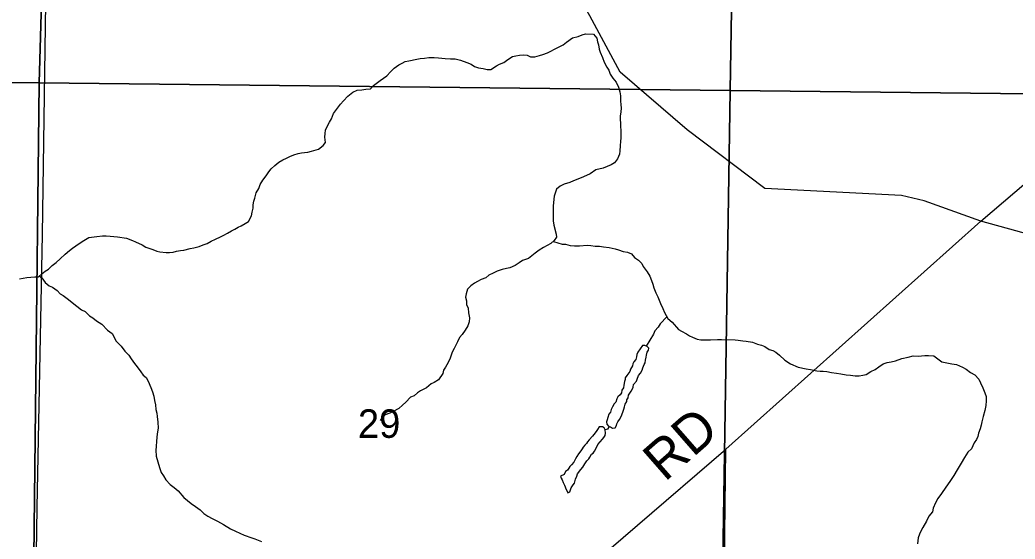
# Model space of a CAD drawing. Extents: x 0 to 34, y 0 to 22.
# Drawn here: x 3.441 to 4.9, y 15.795 to 16.557 of the extents above; entities that cross this region are included whole.
import ezdxf

# ---------------------------------------------------------------- set-up
doc = ezdxf.new("R2010")
doc.units = 0
for name, color, linetype in [('GM_X_County_Road', 7, 'Continuous'), ('GM_X_County_Road_Text', 7, 'Continuous'), ('GM_X_Minor_Lake', 7, 'Continuous'), ('GM_X_Minor_River', 7, 'Continuous'), ('GM_X_Section', 7, 'Continuous'), ('GM_X_Section_Text', 7, 'Continuous'), ('GM_X_State_Route', 7, 'Continuous'), ('GM_X_Township_Road', 7, 'Continuous')]:
    doc.layers.add(name, color=color, linetype=linetype)

msp = doc.modelspace()

# ---------------------------------------------------------------- linework, layer by layer
at = {"layer": 'GM_X_County_Road'}
msp.add_lwpolyline([(3.9812, 15.4992), (4.2172, 15.704), (4.4759, 15.927), (4.8499, 16.2614), (4.9696, 16.3635), (5.1729, 16.5392), (5.2364, 16.5952)], dxfattribs=at)
at = {"layer": 'GM_X_Minor_Lake'}
for points in [[(4.3539, 16.0791), (4.3469, 16.069), (4.3457, 16.0656), (4.3453, 16.0622), (4.344, 16.0585), (4.3413, 16.0551), (4.3398, 16.0521), (4.3393, 16.0494), (4.3362, 16.0442), (4.3354, 16.0408), (4.3307, 16.0352), (4.3287, 16.0318), (4.3283, 16.0292), (4.3275, 16.0262), (4.3266, 16.0209), (4.3258, 16.0171), (4.3238, 16.0137), (4.323, 16.0096), (4.321, 16.0066), (4.3179, 16.0036), (4.3163, 16.0006), (4.3147, 15.9961), (4.3124, 15.9935), (4.31, 15.989), (4.3081, 15.9852), (4.3072, 15.981), (4.3045, 15.9784), (4.3029, 15.9732), (4.3021, 15.9698), (4.3013, 15.9671), (4.3016, 15.9637), (4.3042, 15.9606), (4.305, 15.9604)], [(4.305, 15.9604), (4.3068, 15.9598), (4.3098, 15.9579), (4.3139, 15.9582), (4.3159, 15.9615), (4.3163, 15.9642), (4.3175, 15.9668), (4.3203, 15.9705), (4.3222, 15.9739), (4.3234, 15.9773), (4.3254, 15.9826), (4.3263, 15.9856), (4.3275, 15.989), (4.3283, 15.9928), (4.3307, 15.9969), (4.3311, 15.9995), (4.3327, 16.0022), (4.3335, 16.0063), (4.3351, 16.0089), (4.3374, 16.0119), (4.339, 16.0153), (4.3402, 16.0179), (4.3406, 16.0217), (4.3453, 16.0266), (4.3461, 16.0296), (4.3481, 16.0349), (4.3512, 16.0386), (4.3536, 16.0427), (4.3544, 16.0461), (4.3564, 16.051), (4.3576, 16.0536), (4.3584, 16.0574), (4.3593, 16.0619), (4.3597, 16.0646), (4.3609, 16.0691), (4.3625, 16.0721), (4.3633, 16.0751), (4.3607, 16.0775), (4.3573, 16.0791), (4.3539, 16.0791)], [(4.2905, 15.9598), (4.2878, 15.956), (4.2858, 15.9526), (4.2827, 15.9485), (4.2808, 15.9459), (4.2757, 15.9407), (4.2734, 15.9377), (4.2718, 15.9351), (4.2691, 15.9329), (4.2668, 15.9299), (4.2656, 15.9272), (4.2633, 15.9246), (4.2602, 15.9202), (4.2574, 15.916), (4.2558, 15.9126), (4.2531, 15.9078), (4.25, 15.904), (4.2473, 15.9014), (4.2461, 15.8988), (4.2438, 15.8962), (4.2411, 15.894), (4.2391, 15.8898), (4.2337, 15.8873), (4.2344, 15.8846), (4.2359, 15.8819), (4.2377, 15.8781), (4.2395, 15.8743), (4.2406, 15.8716), (4.2413, 15.8689), (4.2435, 15.8655), (4.2442, 15.8628), (4.2473, 15.8643), (4.2481, 15.8673), (4.2493, 15.8703), (4.252, 15.8744), (4.254, 15.877), (4.2556, 15.8831), (4.2576, 15.8872), (4.2588, 15.8906), (4.2635, 15.8973), (4.2662, 15.9007), (4.2693, 15.9056), (4.2724, 15.9097), (4.2751, 15.9126), (4.2767, 15.9153), (4.2791, 15.9194), (4.2818, 15.9212), (4.2837, 15.9239), (4.2869, 15.9302), (4.2885, 15.934), (4.2951, 15.9415), (4.2974, 15.9441), (4.299, 15.9471), (4.2998, 15.9505), (4.2994, 15.9553)], [(4.2994, 15.9553), (4.2977, 15.9581), (4.2951, 15.9597), (4.2905, 15.9598)]]:
    msp.add_lwpolyline(points, dxfattribs=at)
at = {"layer": 'GM_X_Minor_River'}
for points in [[(3.7841, 16.2908), (3.7853, 16.2954), (3.7876, 16.303), (3.7911, 16.3094), (3.7934, 16.315), (3.7973, 16.3214), (3.8019, 16.3279), (3.8062, 16.3339), (3.8096, 16.3384), (3.8146, 16.3433), (3.8208, 16.3481), (3.8265, 16.3515), (3.8318, 16.3541), (3.8368, 16.3563), (3.8425, 16.3589), (3.849, 16.3608), (3.8539, 16.3615), (3.8585, 16.3622), (3.863, 16.3625), (3.8687, 16.3643), (3.8786, 16.3673), (3.8855, 16.3725), (3.889, 16.377), (3.8883, 16.3846), (3.8884, 16.3903), (3.8892, 16.3949), (3.8915, 16.4005), (3.895, 16.4066), (3.8977, 16.4115), (3.9008, 16.4194), (3.9112, 16.433), (3.9155, 16.4382), (3.922, 16.4446), (3.9293, 16.4506), (3.9354, 16.4536), (3.9422, 16.4543), (3.9483, 16.4553), (3.9551, 16.4557), (3.9597, 16.4605), (3.9693, 16.4677), (3.9743, 16.4714), (3.9789, 16.4748), (3.9842, 16.4804), (3.99, 16.486), (3.9965, 16.4909), (4.0014, 16.4935), (4.006, 16.4957), (4.0113, 16.4968), (4.0228, 16.499), (4.0281, 16.5), (4.0342, 16.5007), (4.0406, 16.5014), (4.0482, 16.5017), (4.055, 16.5009), (4.0645, 16.5), (4.0724, 16.4996), (4.0793, 16.4995), (4.0868, 16.4979), (4.0963, 16.494), (4.1027, 16.4917), (4.1076, 16.4886), (4.1136, 16.4866), (4.1201, 16.4854), (4.1261, 16.4838), (4.1314, 16.4838), (4.1399, 16.4894), (4.1444, 16.4916), (4.1505, 16.4942), (4.1563, 16.4987), (4.1631, 16.5028), (4.1681, 16.5042), (4.1734, 16.5049), (4.1787, 16.5056), (4.1848, 16.5052), (4.1897, 16.5025), (4.1958, 16.5024), (4.203, 16.5046), (4.2079, 16.5061), (4.2148, 16.5083), (4.2194, 16.5109), (4.2251, 16.5139), (4.2297, 16.5161), (4.2377, 16.5202), (4.2427, 16.5239), (4.2511, 16.5303), (4.2594, 16.5325), (4.2655, 16.5347), (4.2701, 16.5362), (4.2822, 16.536), (4.2871, 16.5299), (4.2878, 16.5246), (4.2893, 16.52), (4.2903, 16.5139), (4.2918, 16.5094), (4.2951, 16.5017), (4.2977, 16.4949), (4.3014, 16.4876), (4.3044, 16.483), (4.3066, 16.4773), (4.3103, 16.4712), (4.3152, 16.4655)], [(4.3152, 16.4655), (4.3189, 16.4582), (4.3207, 16.451), (4.3218, 16.4453), (4.3217, 16.4377), (4.322, 16.4324), (4.3224, 16.4274), (4.3219, 16.4217), (4.3211, 16.4157), (4.321, 16.4103), (4.3214, 16.4058), (4.3217, 16.3997), (4.322, 16.3948), (4.3219, 16.3834), (4.3218, 16.3788), (4.3213, 16.372), (4.3209, 16.3648), (4.3204, 16.3599), (4.3173, 16.3527), (4.3127, 16.347), (4.3078, 16.3441), (4.2963, 16.3392), (4.2857, 16.3367), (4.2773, 16.3307), (4.2673, 16.3263), (4.2593, 16.3229), (4.2525, 16.3207), (4.2475, 16.3181), (4.2392, 16.3159), (4.2334, 16.313), (4.2277, 16.3085), (4.2261, 16.3039), (4.2242, 16.2979), (4.2229, 16.2839), (4.2228, 16.2759), (4.2231, 16.2683), (4.223, 16.2618), (4.2237, 16.2554), (4.2273, 16.2424), (4.228, 16.2379), (4.2246, 16.233), (4.2196, 16.2285), (4.2142, 16.2259), (4.2085, 16.2229), (4.2024, 16.2188), (4.1967, 16.2147), (4.1867, 16.2068), (4.1779, 16.2039), (4.173, 16.2001), (4.1672, 16.1964), (4.1592, 16.193), (4.1543, 16.192), (4.1482, 16.1905), (4.141, 16.1879), (4.1349, 16.1853), (4.1288, 16.182), (4.1242, 16.1782), (4.1173, 16.1757), (4.112, 16.1727), (4.1074, 16.1704), (4.102, 16.1667), (4.0971, 16.1618), (4.0955, 16.1546), (4.0946, 16.1501), (4.0957, 16.1444), (4.096, 16.1394), (4.0982, 16.1337), (4.0989, 16.1269), (4.1, 16.1197), (4.0999, 16.1136), (4.0976, 16.1079), (4.0937, 16.1015), (4.0895, 16.0951), (4.0856, 16.0906), (4.0825, 16.0842), (4.0775, 16.0747), (4.0748, 16.0691), (4.072, 16.0604), (4.0689, 16.0539), (4.065, 16.0471), (4.0623, 16.0426), (4.0611, 16.0381), (4.0549, 16.0287), (4.0485, 16.0249), (4.0439, 16.0227), (4.037, 16.0167), (4.0286, 16.0126), (4.024, 16.0096), (4.019, 16.0051), (4.0137, 16.0033), (4.0068, 15.9961), (4.0022, 15.9916), (3.9968, 15.9868), (3.9884, 15.9823), (3.9835, 15.9797), (3.9766, 15.9771), (3.972, 15.9734), (3.9693, 15.9688)], [(3.4406, 16.1769), (3.4459, 16.1779), (3.4513, 16.1786), (3.457, 16.1793), (3.463, 16.1797), (3.468, 16.18), (3.4733, 16.1841), (3.4779, 16.1882), (3.4829, 16.1912), (3.4883, 16.1965), (3.494, 16.201), (3.4998, 16.2062), (3.5074, 16.213), (3.5135, 16.2182), (3.5181, 16.2216), (3.5231, 16.2253), (3.5277, 16.2287), (3.5346, 16.2332), (3.5422, 16.2373), (3.5536, 16.239), (3.562, 16.2397), (3.5673, 16.2397), (3.5733, 16.2392), (3.5839, 16.2383), (3.5972, 16.2363), (3.6059, 16.2332), (3.6104, 16.2312), (3.6202, 16.2269), (3.6255, 16.2231), (3.6357, 16.2199), (3.6417, 16.2176), (3.6463, 16.2164), (3.6554, 16.2155), (3.6603, 16.2155), (3.6656, 16.2162), (3.6706, 16.2173), (3.6763, 16.2184), (3.6812, 16.2191), (3.6907, 16.2212), (3.696, 16.2223), (3.7037, 16.2245), (3.7097, 16.2267), (3.7155, 16.2289), (3.7216, 16.2319), (3.728, 16.2349), (3.7349, 16.2386), (3.7399, 16.2408), (3.7452, 16.2438), (3.7513, 16.2472), (3.7559, 16.2498), (3.7609, 16.2524), (3.7654, 16.2546), (3.7712, 16.258), (3.7761, 16.2609), (3.7804, 16.2692), (3.7816, 16.2745), (3.7828, 16.2806), (3.7832, 16.2855), (3.7841, 16.2908)], [(4.2233, 16.2318), (4.2359, 16.2279), (4.2408, 16.2275), (4.248, 16.2259), (4.2544, 16.2251), (4.2613, 16.2254), (4.2726, 16.226), (4.2783, 16.2256), (4.2844, 16.2247), (4.2908, 16.225), (4.2969, 16.2238), (4.3049, 16.223), (4.3139, 16.221), (4.3185, 16.2194), (4.3257, 16.2171), (4.3317, 16.2159), (4.3377, 16.2135), (4.3422, 16.2082), (4.3479, 16.2043), (4.3528, 16.1993), (4.355, 16.1947), (4.3606, 16.1871), (4.3647, 16.1806), (4.3673, 16.1745), (4.3691, 16.1692), (4.3706, 16.1634), (4.3735, 16.1562), (4.3765, 16.1505), (4.3783, 16.1455), (4.3805, 16.1406), (4.3839, 16.1333), (4.3861, 16.1272), (4.3909, 16.1184), (4.3973, 16.1134), (4.4067, 16.1023), (4.4112, 16.1), (4.4183, 16.0961), (4.4229, 16.093), (4.4274, 16.0911), (4.4342, 16.0884), (4.4395, 16.0875), (4.4535, 16.0874), (4.4641, 16.0877), (4.4698, 16.0876), (4.4896, 16.0874), (4.4941, 16.087), (4.5009, 16.0861), (4.5058, 16.0853), (4.5153, 16.0837), (4.5225, 16.081), (4.5282, 16.0794), (4.5331, 16.0774), (4.5395, 16.0732), (4.5448, 16.0716), (4.5493, 16.0693), (4.5549, 16.0647), (4.5628, 16.0574), (4.5707, 16.0523), (4.5824, 16.0473), (4.5938, 16.0449), (4.6002, 16.0437), (4.6097, 16.0417), (4.6142, 16.0413), (4.6188, 16.0412), (4.6241, 16.0408), (4.6309, 16.0396), (4.6385, 16.0383), (4.6445, 16.0375), (4.6525, 16.0359), (4.6589, 16.0355), (4.6657, 16.0346), (4.6718, 16.0346), (4.6771, 16.0356), (4.6817, 16.0367), (4.6885, 16.0408), (4.695, 16.0438), (4.7004, 16.0475), (4.7069, 16.052), (4.7126, 16.0542), (4.7183, 16.0553), (4.7251, 16.0564), (4.7343, 16.0601), (4.7434, 16.0619), (4.751, 16.0637), (4.7586, 16.0636), (4.7632, 16.064), (4.7681, 16.0643), (4.7734, 16.0642), (4.781, 16.0638), (4.793, 16.0553), (4.8025, 16.0529), (4.8074, 16.0521), (4.8142, 16.0509), (4.8188, 16.0493), (4.8233, 16.0474), (4.8286, 16.0443), (4.835, 16.0396), (4.841, 16.0358), (4.847, 16.0296), (4.8496, 16.0243), (4.8529, 16.0167)], [(3.4693, 16.181), (3.4729, 16.1784), (3.4781, 16.1715), (3.4841, 16.1665), (3.4887, 16.1646), (3.4954, 16.1596), (3.4999, 16.1546), (3.5044, 16.1523), (3.5123, 16.1465), (3.5176, 16.1422), (3.5244, 16.1365), (3.5311, 16.1315), (3.5368, 16.1287), (3.5432, 16.1226), (3.5477, 16.1195), (3.5533, 16.1153), (3.5613, 16.1103), (3.5695, 16.1014), (3.5763, 16.0968), (3.5822, 16.0854), (3.5893, 16.0781), (3.5949, 16.0708), (3.6006, 16.065), (3.6039, 16.0593), (3.6091, 16.0524), (3.6129, 16.0475), (3.6185, 16.0406), (3.6215, 16.0356), (3.626, 16.0321), (3.629, 16.0268), (3.633, 16.0172), (3.6352, 16.0111), (3.6374, 16.0047), (3.6381, 15.9982), (3.6396, 15.9921), (3.6402, 15.9849), (3.6417, 15.9799), (3.6424, 15.975), (3.6434, 15.9666), (3.6437, 15.9575), (3.6421, 15.9496), (3.6412, 15.9386), (3.6408, 15.931), (3.6403, 15.9253), (3.6406, 15.9166), (3.6432, 15.9082), (3.6457, 15.9002), (3.6479, 15.8926), (3.6517, 15.888), (3.655, 15.8819), (3.6614, 15.8753), (3.6674, 15.8707), (3.673, 15.8657), (3.6813, 15.8561), (3.6922, 15.8473), (3.6986, 15.8427), (3.7053, 15.838), (3.7109, 15.8323), (3.7166, 15.8288), (3.723, 15.8253), (3.7306, 15.8214), (3.7351, 15.8187), (3.7396, 15.8164), (3.7498, 15.8099), (3.7573, 15.8067), (3.7698, 15.8005), (3.7811, 15.797), (3.7856, 15.7954), (3.7951, 15.7915)], [(4.3894, 16.1212), (4.3798, 16.1106), (4.3767, 16.1061), (4.3721, 16.1004), (4.3698, 16.0955), (4.3594, 16.0781)], [(4.8529, 16.0167), (4.8558, 16.0094), (4.8577, 16.0041), (4.858, 15.998), (4.8572, 15.9912), (4.8559, 15.9836), (4.8536, 15.9749), (4.8516, 15.967), (4.8504, 15.962), (4.8492, 15.9567), (4.8468, 15.9503), (4.8456, 15.9454), (4.8437, 15.9409), (4.8402, 15.936), (4.8363, 15.9276), (4.831, 15.9224), (4.8263, 15.9148), (4.8213, 15.9065), (4.8182, 15.9013), (4.8155, 15.8967), (4.8105, 15.8884), (4.8047, 15.8794), (4.7985, 15.8711), (4.7923, 15.8621), (4.7869, 15.8545), (4.7835, 15.8481), (4.78, 15.8406), (4.7791, 15.8352), (4.7738, 15.8285), (4.7703, 15.8213), (4.7648, 15.8122), (4.7621, 15.8066), (4.7602, 15.802), (4.7582, 15.7968), (4.757, 15.788)], [(4.305, 15.9604), (4.3025, 15.9561), (4.2994, 15.9553)]]:
    msp.add_lwpolyline(points, dxfattribs=at)
at = {"layer": 'GM_X_Section'}
for points in [[(3.4982, 17.462), (3.4692, 16.4646), (2.4877, 16.4726), (2.5103, 17.4328), (2.5117, 17.4662)], [(4.4991, 17.4554), (4.4826, 16.453), (3.4692, 16.4646), (3.4982, 17.462)], [(5.5087, 17.4571), (5.4956, 16.4418), (4.4826, 16.453), (4.4991, 17.4554)], [(3.4692, 16.4646), (3.4584, 15.5077), (2.4379, 15.527), (2.4859, 16.423), (2.4877, 16.4726)], [(4.4826, 16.453), (4.4671, 15.4814), (3.4584, 15.5077), (3.4692, 16.4646)], [(5.4956, 16.4418), (5.4878, 15.4398), (4.4671, 15.4814), (4.4826, 16.453)]]:
    msp.add_lwpolyline(points, close=True, dxfattribs=at)
at = {"layer": 'GM_X_State_Route'}
msp.add_lwpolyline([(3.462, 15.1881), (3.4615, 15.5078), (3.4661, 15.8411), (3.4739, 16.2421), (3.4802, 16.6496)], dxfattribs=at)
at = {"layer": 'GM_X_Township_Road'}
msp.add_line((4.4706, 15.4769), (4.4759, 15.927), dxfattribs=at)
msp.add_lwpolyline([(5.5412, 15.849), (5.3873, 16.0366), (5.2909, 16.1369), (5.2777, 16.144), (5.2615, 16.1488), (5.2562, 16.1504), (5.2509, 16.1531), (5.2324, 16.1576), (5.1579, 16.1763), (4.8499, 16.2614), (4.7668, 16.2912), (4.7336, 16.2989), (4.5333, 16.3094), (4.4196, 16.3955), (4.3211, 16.4799), (4.2769, 16.5627), (4.2296, 16.6459), (4.2272, 16.6847), (4.2269, 16.7584)], dxfattribs=at)

# ---------------------------------------------------------------- texts
at = {"layer": 'GM_X_County_Road_Text'}
msp.add_text('RD', height=0.05682, rotation=41.14, dxfattribs=at).set_placement((4.3865, 15.878))
at = {"layer": 'GM_X_Section_Text'}
msp.add_text('29', height=0.04186, rotation=0, dxfattribs=at).set_placement((3.9366, 15.9435))

doc.saveas('drawing.dxf')
